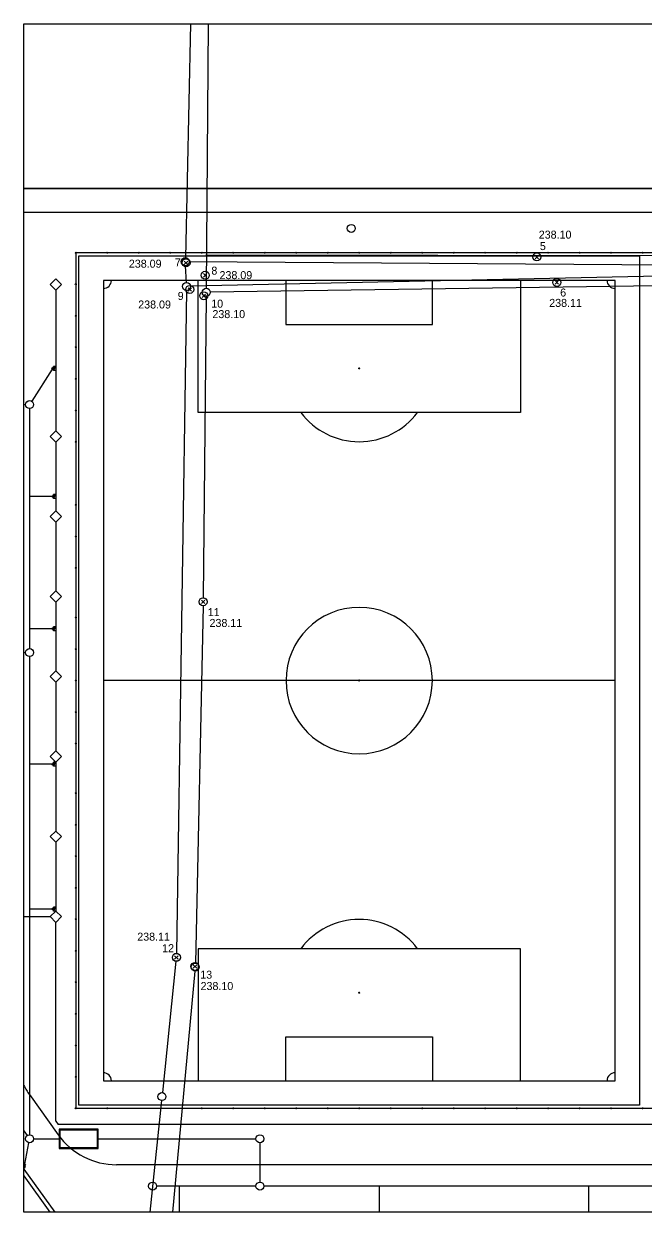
# Model space of a CAD drawing. Extents: x -264125 to -263915, y -1242307 to -1242159.
# Drawn here: x -264124.6 to -264047.1, y -1242307.4 to -1242158.9 of the extents above; entities that cross this region are included whole.
import ezdxf

# ---------------------------------------------------------------- set-up
doc = ezdxf.new("R2010")
doc.units = 0
for name, color, linetype in [('KFA_BODY_CISLO', 7, 'Continuous'), ('KFA_BODY_SYMBOL', 7, 'Continuous'), ('KFA_BODY_VYSKA', 7, 'Continuous'), ('KFA_JESTV_IS_DSP', 7, 'Continuous'), ('KFA_SITUACIA_DSP', 7, 'Continuous'), ('KFA_SO_40-3_SACHTY_POKLOPY', 7, 'Continuous'), ('RAM_NA_TLAC_A3_1-500', 7, 'Continuous')]:
    doc.layers.add(name, color=color, linetype=linetype)

msp = doc.modelspace()

# ---------------------------------------------------------------- linework, layer by layer
at = {"layer": 'KFA_BODY_SYMBOL'}
for p, q in [((-264104.51, -1242189), (-264104.06, -1242188.56)), ((-264104.06, -1242189), (-264104.51, -1242188.56)), ((-264060.62, -1242188.27), (-264060.18, -1242187.83)), ((-264060.18, -1242188.27), (-264060.62, -1242187.83)), ((-264102.1, -1242190.56), (-264101.66, -1242190.12)), ((-264101.66, -1242190.56), (-264102.1, -1242190.12)), ((-264104.03, -1242192.33), (-264103.59, -1242191.89)), ((-264103.59, -1242192.33), (-264104.03, -1242191.89)), ((-264058.12, -1242191.45), (-264057.68, -1242191.01)), ((-264057.68, -1242191.45), (-264058.12, -1242191.01)), ((-264102.28, -1242193.12), (-264101.84, -1242192.68)), ((-264101.84, -1242193.12), (-264102.28, -1242192.68)), ((-264102.36, -1242231.36), (-264101.92, -1242230.92)), ((-264101.92, -1242231.36), (-264102.36, -1242230.92)), ((-264105.72, -1242275.8), (-264105.27, -1242275.36)), ((-264105.27, -1242275.8), (-264105.72, -1242275.36)), ((-264103.38, -1242276.92), (-264102.94, -1242276.48)), ((-264102.94, -1242276.92), (-264103.38, -1242276.48))]:
    msp.add_line(p, q, dxfattribs=at)
at = {"layer": 'KFA_JESTV_IS_DSP'}
for p, q in [((-264103.74, -1242158.91), (-264104.36, -1242188.14)), ((-264101.53, -1242158.91), (-264101.75, -1242191.96)), ((-264014.6, -1242189.3), (-264103.87, -1242188.64)), ((-264014.74, -1242187.97), (-264101.79, -1242187.81)), ((-264104.37, -1242189.14), (-264104.25, -1242191.23)), ((-264045.1, -1242190.47), (-264103.72, -1242191.72)), ((-264045.33, -1242191.64), (-264101.25, -1242192.45)), ((-264104.23, -1242192.23), (-264105.48, -1242275.06)), ((-264101.76, -1242192.96), (-264102.14, -1242230.64)), ((-264102.15, -1242231.64), (-264103.11, -1242276.28)), ((-264105.54, -1242276.06), (-264107.24, -1242292.46)), ((-264103.16, -1242277.28), (-264105.98, -1242307.41)), ((-264107.35, -1242293.45), (-264108.79, -1242307.41))]:
    msp.add_line(p, q, dxfattribs=at)
for centre in [(-264083.61, -1242184.48), (-264104.37, -1242188.64), (-264104.22, -1242191.73), (-264101.75, -1242192.46), (-264102.14, -1242231.14), (-264105.49, -1242275.56), (-264103.12, -1242276.78), (-264107.29, -1242292.96)]:
    msp.add_circle(centre, 0.5, dxfattribs=at)
at = {"layer": 'KFA_SITUACIA_DSP'}
for p, q in [((-264077.23, -1242179.48), (-264124.58, -1242179.48)), ((-264124.58, -1242179.48), (-263959.47, -1242179.48)), ((-263959.47, -1242179.48), (-264124.58, -1242179.48)), ((-263959.47, -1242179.48), (-264077.23, -1242179.48)), ((-264045.2, -1242182.48), (-264124.58, -1242182.48)), ((-264118.01, -1242187.53), (-264118.13, -1242187.53)), ((-264118.07, -1242187.59), (-264118.07, -1242187.47)), ((-263972.07, -1242187.53), (-264118.07, -1242187.53)), ((-264118.07, -1242187.53), (-264118.07, -1242294.43)), ((-264114.07, -1242187.53), (-264114.19, -1242187.53)), ((-264114.13, -1242187.59), (-264114.13, -1242187.47)), ((-264110.13, -1242187.53), (-264110.25, -1242187.53)), ((-264110.19, -1242187.59), (-264110.19, -1242187.47)), ((-264106.19, -1242187.53), (-264106.31, -1242187.53)), ((-264106.25, -1242187.59), (-264106.25, -1242187.47)), ((-264102.25, -1242187.53), (-264102.37, -1242187.53)), ((-264102.31, -1242187.59), (-264102.31, -1242187.47)), ((-264098.31, -1242187.53), (-264098.43, -1242187.53)), ((-264098.37, -1242187.59), (-264098.37, -1242187.47)), ((-264094.37, -1242187.53), (-264094.49, -1242187.53)), ((-264094.43, -1242187.59), (-264094.43, -1242187.47)), ((-264090.44, -1242187.53), (-264090.56, -1242187.53)), ((-264090.5, -1242187.59), (-264090.5, -1242187.47)), ((-264086.5, -1242187.53), (-264086.62, -1242187.53)), ((-264086.56, -1242187.59), (-264086.56, -1242187.47)), ((-264082.56, -1242187.53), (-264082.68, -1242187.53)), ((-264082.62, -1242187.59), (-264082.62, -1242187.47)), ((-264078.62, -1242187.53), (-264078.74, -1242187.53)), ((-264078.68, -1242187.59), (-264078.68, -1242187.47)), ((-264074.68, -1242187.53), (-264074.8, -1242187.53)), ((-264074.74, -1242187.59), (-264074.74, -1242187.47)), ((-264070.74, -1242187.53), (-264070.86, -1242187.53)), ((-264070.8, -1242187.59), (-264070.8, -1242187.47)), ((-264066.8, -1242187.53), (-264066.92, -1242187.53)), ((-264066.86, -1242187.59), (-264066.86, -1242187.47)), ((-264062.86, -1242187.53), (-264062.98, -1242187.53)), ((-264062.92, -1242187.59), (-264062.92, -1242187.47)), ((-264058.92, -1242187.53), (-264059.04, -1242187.53)), ((-264058.98, -1242187.59), (-264058.98, -1242187.47)), ((-264054.99, -1242187.53), (-264055.11, -1242187.53)), ((-264055.05, -1242187.59), (-264055.05, -1242187.47)), ((-264051.05, -1242187.53), (-264051.17, -1242187.53)), ((-264051.11, -1242187.59), (-264051.11, -1242187.47)), ((-264047.11, -1242187.53), (-264047.23, -1242187.53)), ((-264047.17, -1242187.59), (-264047.17, -1242187.47)), ((-264117.67, -1242187.93), (-264047.57, -1242187.93)), ((-264117.67, -1242294.03), (-264117.67, -1242187.93)), ((-264047.57, -1242187.93), (-264047.57, -1242294.03)), ((-264121.27, -1242191.48), (-264120.57, -1242190.78)), ((-264120.57, -1242192.19), (-264121.27, -1242191.48)), ((-264120.57, -1242190.78), (-264119.86, -1242191.48)), ((-264119.86, -1242191.48), (-264120.57, -1242192.19)), ((-264118.01, -1242191.47), (-264118.13, -1242191.47)), ((-264118.07, -1242191.41), (-264118.07, -1242191.53)), ((-264050.62, -1242190.98), (-264114.62, -1242190.98)), ((-264114.62, -1242190.98), (-264114.62, -1242290.98)), ((-264102.78, -1242207.48), (-264102.78, -1242190.98)), ((-264091.78, -1242190.98), (-264091.78, -1242196.48)), ((-264073.46, -1242196.48), (-264073.46, -1242190.98)), ((-264062.46, -1242190.98), (-264062.46, -1242207.48)), ((-264050.62, -1242290.98), (-264050.62, -1242190.98)), ((-264120.57, -1242192.19), (-264120.57, -1242209.78)), ((-264118.01, -1242195.41), (-264118.13, -1242195.41)), ((-264118.07, -1242195.35), (-264118.07, -1242195.47)), ((-264091.78, -1242196.48), (-264073.46, -1242196.48)), ((-264118.01, -1242199.34), (-264118.13, -1242199.34)), ((-264118.07, -1242199.28), (-264118.07, -1242199.4)), ((-264121.01, -1242202.07), (-264123.58, -1242206.08)), ((-264120.86, -1242202.23), (-264120.86, -1242201.73)), ((-264120.86, -1242201.73), (-264120.57, -1242201.73)), ((-264120.86, -1242202.23), (-264120.57, -1242201.73)), ((-264120.86, -1242202.23), (-264120.57, -1242201.73)), ((-264120.57, -1242201.73), (-264120.86, -1242201.73)), ((-264120.86, -1242201.73), (-264120.86, -1242202.23)), ((-264120.57, -1242202.23), (-264120.86, -1242202.23)), ((-264120.57, -1242201.73), (-264120.57, -1242202.23)), ((-264118.01, -1242203.28), (-264118.13, -1242203.28)), ((-264118.07, -1242203.22), (-264118.07, -1242203.34)), ((-264124.58, -1242206.48), (-264124.35, -1242206.48)), ((-264123.85, -1242207), (-264123.85, -1242236.98)), ((-264118.01, -1242207.22), (-264118.13, -1242207.22)), ((-264118.07, -1242207.16), (-264118.07, -1242207.28)), ((-264062.46, -1242207.48), (-264102.78, -1242207.48)), ((-264121.27, -1242210.48), (-264120.57, -1242209.78)), ((-264120.57, -1242209.78), (-264119.86, -1242210.48)), ((-264120.57, -1242211.19), (-264121.27, -1242210.48)), ((-264119.86, -1242210.48), (-264120.57, -1242211.19)), ((-264120.57, -1242211.19), (-264120.57, -1242219.77)), ((-264118.01, -1242211.16), (-264118.13, -1242211.16)), ((-264118.07, -1242211.1), (-264118.07, -1242211.22)), ((-264121.06, -1242217.98), (-264123.85, -1242217.98)), ((-264120.86, -1242218.23), (-264120.86, -1242217.73)), ((-264120.86, -1242217.73), (-264120.57, -1242217.73)), ((-264120.86, -1242218.23), (-264120.57, -1242217.73)), ((-264120.86, -1242218.23), (-264120.57, -1242217.73)), ((-264120.57, -1242217.73), (-264120.86, -1242217.73)), ((-264120.86, -1242217.73), (-264120.86, -1242218.23)), ((-264120.57, -1242218.23), (-264120.86, -1242218.23)), ((-264120.57, -1242217.73), (-264120.57, -1242218.23)), ((-264121.27, -1242220.48), (-264120.57, -1242219.78)), ((-264120.57, -1242219.78), (-264119.86, -1242220.48)), ((-264118.01, -1242219.03), (-264118.13, -1242219.03)), ((-264118.07, -1242218.97), (-264118.07, -1242219.09)), ((-264120.57, -1242221.19), (-264121.27, -1242220.48)), ((-264119.86, -1242220.48), (-264120.57, -1242221.19)), ((-264120.57, -1242221.19), (-264120.57, -1242229.77)), ((-264118.01, -1242222.97), (-264118.13, -1242222.97)), ((-264118.07, -1242222.91), (-264118.07, -1242223.03)), ((-264118.01, -1242226.91), (-264118.13, -1242226.91)), ((-264118.07, -1242226.85), (-264118.07, -1242226.97)), ((-264121.27, -1242230.48), (-264120.57, -1242229.78)), ((-264120.57, -1242231.19), (-264121.27, -1242230.48)), ((-264120.57, -1242229.78), (-264119.86, -1242230.48)), ((-264119.86, -1242230.48), (-264120.57, -1242231.19)), ((-264120.57, -1242231.19), (-264120.57, -1242239.77)), ((-264118.01, -1242233.11), (-264118.13, -1242233.11)), ((-264118.07, -1242233.05), (-264118.07, -1242233.17)), ((-264121.06, -1242234.5), (-264123.85, -1242234.5)), ((-264120.86, -1242234.75), (-264120.86, -1242234.25)), ((-264120.86, -1242234.25), (-264120.57, -1242234.25)), ((-264120.86, -1242234.75), (-264120.57, -1242234.25)), ((-264120.86, -1242234.75), (-264120.57, -1242234.25)), ((-264120.57, -1242234.25), (-264120.86, -1242234.25)), ((-264120.86, -1242234.25), (-264120.86, -1242234.75)), ((-264120.57, -1242234.75), (-264120.86, -1242234.75)), ((-264120.57, -1242234.25), (-264120.57, -1242234.75)), ((-264124.58, -1242237.48), (-264124.35, -1242237.48)), ((-264123.85, -1242237.98), (-264123.85, -1242297.74)), ((-264118.01, -1242237.04), (-264118.13, -1242237.04)), ((-264118.07, -1242236.98), (-264118.07, -1242237.1)), ((-264121.27, -1242240.48), (-264120.57, -1242239.78)), ((-264120.57, -1242241.19), (-264121.27, -1242240.48)), ((-264120.57, -1242239.78), (-264119.86, -1242240.48)), ((-264119.86, -1242240.48), (-264120.57, -1242241.19)), ((-264118.01, -1242240.98), (-264118.13, -1242240.98)), ((-264118.07, -1242241.04), (-264118.07, -1242240.92)), ((-264050.62, -1242240.98), (-264114.62, -1242240.98)), ((-264120.57, -1242241.19), (-264120.57, -1242249.77)), ((-264118.01, -1242244.92), (-264118.13, -1242244.92)), ((-264118.07, -1242244.98), (-264118.07, -1242244.86)), ((-264121.27, -1242250.48), (-264120.57, -1242249.78)), ((-264120.57, -1242249.78), (-264119.86, -1242250.48)), ((-264118.01, -1242248.86), (-264118.13, -1242248.86)), ((-264118.07, -1242248.92), (-264118.07, -1242248.8)), ((-264121.06, -1242251.44), (-264123.85, -1242251.44)), ((-264120.57, -1242251.19), (-264121.27, -1242250.48)), ((-264120.86, -1242251.69), (-264120.86, -1242251.19)), ((-264120.86, -1242251.19), (-264120.57, -1242251.19)), ((-264120.86, -1242251.69), (-264120.57, -1242251.19)), ((-264120.86, -1242251.69), (-264120.57, -1242251.19)), ((-264120.57, -1242251.19), (-264120.86, -1242251.19)), ((-264120.86, -1242251.19), (-264120.86, -1242251.69)), ((-264119.86, -1242250.48), (-264120.57, -1242251.19)), ((-264120.57, -1242251.19), (-264120.57, -1242251.69)), ((-264120.57, -1242251.19), (-264120.57, -1242259.78)), ((-264120.57, -1242251.69), (-264120.86, -1242251.69)), ((-264118.01, -1242255.06), (-264118.13, -1242255.06)), ((-264118.07, -1242255.12), (-264118.07, -1242255)), ((-264121.27, -1242260.48), (-264120.57, -1242259.78)), ((-264120.57, -1242259.78), (-264119.86, -1242260.48)), ((-264118.01, -1242258.99), (-264118.13, -1242258.99)), ((-264118.07, -1242259.05), (-264118.07, -1242258.93)), ((-264120.57, -1242261.19), (-264121.27, -1242260.48)), ((-264119.86, -1242260.48), (-264120.57, -1242261.19)), ((-264120.57, -1242261.19), (-264120.57, -1242269.77)), ((-264118.01, -1242262.93), (-264118.13, -1242262.93)), ((-264118.07, -1242262.99), (-264118.07, -1242262.87)), ((-264118.01, -1242266.87), (-264118.13, -1242266.87)), ((-264118.07, -1242266.93), (-264118.07, -1242266.81)), ((-264120.86, -1242269.78), (-264120.86, -1242269.28)), ((-264120.86, -1242269.28), (-264120.57, -1242269.28)), ((-264120.86, -1242269.78), (-264120.57, -1242269.28)), ((-264120.86, -1242269.78), (-264120.57, -1242269.28)), ((-264120.57, -1242269.28), (-264120.86, -1242269.28)), ((-264120.86, -1242269.28), (-264120.86, -1242269.78)), ((-264120.57, -1242269.28), (-264120.57, -1242269.78)), ((-264124.58, -1242270.48), (-264121.27, -1242270.48)), ((-264121.06, -1242269.53), (-264123.85, -1242269.53)), ((-264121.27, -1242270.48), (-264120.57, -1242269.78)), ((-264120.57, -1242271.19), (-264121.27, -1242270.48)), ((-264120.57, -1242269.78), (-264120.86, -1242269.78)), ((-264120.57, -1242269.78), (-264119.86, -1242270.48)), ((-264119.86, -1242270.48), (-264120.57, -1242271.19)), ((-264118.01, -1242270.81), (-264118.13, -1242270.81)), ((-264118.07, -1242270.87), (-264118.07, -1242270.75)), ((-264120.57, -1242296.04), (-264120.57, -1242271.19)), ((-264120.57, -1242271.19), (-264120.57, -1242271.19)), ((-264118.01, -1242274.74), (-264118.13, -1242274.74)), ((-264118.07, -1242274.8), (-264118.07, -1242274.68)), ((-264062.46, -1242274.48), (-264102.78, -1242274.48)), ((-264102.78, -1242274.48), (-264102.78, -1242290.98)), ((-264062.46, -1242290.98), (-264062.46, -1242274.48)), ((-264118.01, -1242278.68), (-264118.13, -1242278.68)), ((-264118.07, -1242278.74), (-264118.07, -1242278.62)), ((-264118.01, -1242282.62), (-264118.13, -1242282.62)), ((-264118.07, -1242282.68), (-264118.07, -1242282.56)), ((-264091.78, -1242290.98), (-264091.78, -1242285.48)), ((-264091.78, -1242285.48), (-264073.46, -1242285.48)), ((-264073.46, -1242285.48), (-264073.46, -1242290.98)), ((-264118.01, -1242286.56), (-264118.13, -1242286.56)), ((-264118.07, -1242286.62), (-264118.07, -1242286.5)), ((-264118.01, -1242290.49), (-264118.13, -1242290.49)), ((-264118.07, -1242290.55), (-264118.07, -1242290.43)), ((-264114.62, -1242290.98), (-264050.62, -1242290.98)), ((-264123.87, -1242292.72), (-264120.27, -1242297.74)), ((-264118.01, -1242294.43), (-264118.13, -1242294.43)), ((-264118.07, -1242294.49), (-264118.07, -1242294.37)), ((-264118.07, -1242294.43), (-264045.12, -1242294.43)), ((-264047.57, -1242294.03), (-264117.67, -1242294.03)), ((-264114.07, -1242294.43), (-264114.19, -1242294.43)), ((-264114.13, -1242294.49), (-264114.13, -1242294.37)), ((-264102.25, -1242294.43), (-264102.37, -1242294.43)), ((-264102.31, -1242294.49), (-264102.31, -1242294.37)), ((-264098.31, -1242294.43), (-264098.43, -1242294.43)), ((-264098.37, -1242294.49), (-264098.37, -1242294.37)), ((-264094.37, -1242294.43), (-264094.49, -1242294.43)), ((-264094.43, -1242294.49), (-264094.43, -1242294.37)), ((-264090.44, -1242294.43), (-264090.56, -1242294.43)), ((-264090.5, -1242294.49), (-264090.5, -1242294.37)), ((-264086.5, -1242294.43), (-264086.62, -1242294.43)), ((-264086.56, -1242294.49), (-264086.56, -1242294.37)), ((-264082.56, -1242294.43), (-264082.68, -1242294.43)), ((-264082.62, -1242294.49), (-264082.62, -1242294.37)), ((-264078.62, -1242294.43), (-264078.74, -1242294.43)), ((-264078.68, -1242294.49), (-264078.68, -1242294.37)), ((-264074.68, -1242294.43), (-264074.8, -1242294.43)), ((-264074.74, -1242294.49), (-264074.74, -1242294.37)), ((-264070.74, -1242294.43), (-264070.86, -1242294.43)), ((-264070.8, -1242294.49), (-264070.8, -1242294.37)), ((-264066.8, -1242294.43), (-264066.92, -1242294.43)), ((-264066.86, -1242294.49), (-264066.86, -1242294.37)), ((-264062.86, -1242294.43), (-264062.98, -1242294.43)), ((-264062.92, -1242294.49), (-264062.92, -1242294.37)), ((-264058.92, -1242294.43), (-264059.04, -1242294.43)), ((-264058.98, -1242294.49), (-264058.98, -1242294.37)), ((-264054.99, -1242294.43), (-264055.11, -1242294.43)), ((-264055.05, -1242294.49), (-264055.05, -1242294.37)), ((-264051.05, -1242294.43), (-264051.17, -1242294.43)), ((-264051.11, -1242294.49), (-264051.11, -1242294.37)), ((-264047.11, -1242294.43), (-264047.23, -1242294.43)), ((-264047.17, -1242294.49), (-264047.17, -1242294.37)), ((-264120.57, -1242296.04), (-264120.28, -1242296.43)), ((-264124.58, -1242297.23), (-264124.15, -1242297.83)), ((-264124.58, -1242297.23), (-264124.15, -1242297.83)), ((-264120.02, -1242296.43), (-264120.28, -1242296.43)), ((-264120.15, -1242297.04), (-264120.15, -1242299.44)), ((-264115.25, -1242297.04), (-264120.15, -1242297.04)), ((-264115.35, -1242297.14), (-264120.05, -1242297.14)), ((-264120.05, -1242297.14), (-264120.05, -1242299.34)), ((-264019.58, -1242296.43), (-264120.02, -1242296.43)), ((-264115.35, -1242299.34), (-264115.35, -1242297.14)), ((-264115.25, -1242299.44), (-264115.25, -1242297.04)), ((-264124.44, -1242301.41), (-264123.95, -1242298.73)), ((-264123.35, -1242298.24), (-264120.15, -1242298.24)), ((-264115.25, -1242298.24), (-264095.53, -1242298.24)), ((-264095.03, -1242298.74), (-264095.03, -1242303.65)), ((-264120.15, -1242299.44), (-264115.25, -1242299.44)), ((-264120.05, -1242299.34), (-264115.35, -1242299.34)), ((-264124.58, -1242301.52), (-264124.4, -1242301.77)), ((-264124.4, -1242301.77), (-264124.58, -1242301.52)), ((-264124.4, -1242301.77), (-264124.58, -1242301.9)), ((-264124.58, -1242301.9), (-264124.4, -1242301.77)), ((-264019.58, -1242301.48), (-264112.96, -1242301.48)), ((-264124.58, -1242302.02), (-264120.7, -1242307.41)), ((-264124.58, -1242302.87), (-264121.32, -1242307.41)), ((-264095.53, -1242304.15), (-264107.96, -1242304.15)), ((-264105.08, -1242307.41), (-264105.08, -1242304.15)), ((-264045.53, -1242304.15), (-264094.53, -1242304.15)), ((-264080.08, -1242307.41), (-264080.08, -1242304.15)), ((-264053.91, -1242307.41), (-264053.91, -1242304.15))]:
    msp.add_line(p, q, dxfattribs=at)
for centre, radius in [((-264118.07, -1242187.53), 0.06), ((-264114.13, -1242187.53), 0.06), ((-264110.19, -1242187.53), 0.06), ((-264106.25, -1242187.53), 0.06), ((-264102.31, -1242187.53), 0.06), ((-264098.37, -1242187.53), 0.06), ((-264094.43, -1242187.53), 0.06), ((-264090.5, -1242187.53), 0.06), ((-264086.56, -1242187.53), 0.06), ((-264082.62, -1242187.53), 0.06), ((-264078.68, -1242187.53), 0.06), ((-264074.74, -1242187.53), 0.06), ((-264070.8, -1242187.53), 0.06), ((-264066.86, -1242187.53), 0.06), ((-264062.92, -1242187.53), 0.06), ((-264058.98, -1242187.53), 0.06), ((-264055.05, -1242187.53), 0.06), ((-264051.11, -1242187.53), 0.06), ((-264047.17, -1242187.53), 0.06), ((-264118.07, -1242191.47), 0.06), ((-264118.07, -1242195.41), 0.06), ((-264118.07, -1242199.34), 0.06), ((-264120.96, -1242201.98), 0.1), ((-264082.62, -1242201.98), 0.06), ((-264118.07, -1242203.28), 0.06), ((-264123.85, -1242206.5), 0.5), ((-264118.07, -1242207.22), 0.06), ((-264118.07, -1242211.16), 0.06), ((-264120.96, -1242217.98), 0.1), ((-264118.07, -1242219.03), 0.06), ((-264118.07, -1242222.97), 0.06), ((-264118.07, -1242226.91), 0.06), ((-264118.07, -1242233.11), 0.06), ((-264120.96, -1242234.5), 0.1), ((-264123.85, -1242237.48), 0.5), ((-264118.07, -1242237.04), 0.06), ((-264118.07, -1242240.98), 0.06), ((-264118.07, -1242244.92), 0.06), ((-264118.07, -1242248.86), 0.06), ((-264120.96, -1242251.44), 0.1), ((-264118.07, -1242255.06), 0.06), ((-264118.07, -1242258.99), 0.06), ((-264118.07, -1242262.93), 0.06), ((-264118.07, -1242266.87), 0.06), ((-264120.96, -1242269.53), 0.1), ((-264118.07, -1242270.81), 0.06), ((-264118.07, -1242274.74), 0.06), ((-264118.07, -1242278.68), 0.06), ((-264082.62, -1242279.98), 0.06), ((-264118.07, -1242282.62), 0.06), ((-264118.07, -1242286.56), 0.06), ((-264118.07, -1242290.49), 0.06), ((-264118.07, -1242294.43), 0.06), ((-264114.13, -1242294.43), 0.06), ((-264102.31, -1242294.43), 0.06), ((-264098.37, -1242294.43), 0.06), ((-264094.43, -1242294.43), 0.06), ((-264090.5, -1242294.43), 0.06), ((-264086.56, -1242294.43), 0.06), ((-264082.62, -1242294.43), 0.06), ((-264078.68, -1242294.43), 0.06), ((-264074.74, -1242294.43), 0.06), ((-264070.8, -1242294.43), 0.06), ((-264066.86, -1242294.43), 0.06), ((-264062.92, -1242294.43), 0.06), ((-264058.98, -1242294.43), 0.06), ((-264055.05, -1242294.43), 0.06), ((-264051.11, -1242294.43), 0.06), ((-264047.17, -1242294.43), 0.06), ((-264123.85, -1242298.24), 0.5), ((-264095.03, -1242298.24), 0.5), ((-264124.46, -1242301.51), 0.1), ((-264108.46, -1242304.15), 0.5), ((-264095.03, -1242304.15), 0.5)]:
    msp.add_circle(centre, radius, dxfattribs=at)
for centre, radius, start, end in [((-264114.62, -1242190.98), 1, 270, 360), ((-264050.62, -1242190.98), 1, 180, 270), ((-264082.62, -1242201.98), 0.0303, 90, 270), ((-264082.62, -1242201.98), 0.0303, 270, 90), ((-264082.62, -1242201.98), 9.15, 216.9482, 323.0518), ((-264082.62, -1242240.98), 9.15, 360, 180), ((-264082.62, -1242240.98), 9.15, 180, 360), ((-264082.62, -1242240.98), 0.0605, 90, 270), ((-264082.62, -1242240.98), 0.0605, 270, 90), ((-264082.62, -1242279.98), 9.15, 36.9482, 143.0518), ((-264082.62, -1242279.98), 0.0303, 90, 270), ((-264082.62, -1242279.98), 0.0303, 270, 90), ((-264114.62, -1242290.98), 1, 0, 90), ((-264050.62, -1242290.98), 1, 90, 180), ((-264116.57, -1242287.47), 9, 207.1096, 215.724), ((-264112.96, -1242292.48), 9, 215.724, 270)]:
    msp.add_arc(centre, radius, start, end, dxfattribs=at)
at = {"layer": 'KFA_SO_40-3_SACHTY_POKLOPY'}
for centre in [(-264060.4, -1242188.05), (-264104.28, -1242188.78), (-264101.88, -1242190.34), (-264103.81, -1242192.11), (-264057.9, -1242191.23), (-264102.06, -1242192.9), (-264102.14, -1242231.14), (-264105.49, -1242275.58), (-264103.16, -1242276.7)]:
    msp.add_circle(centre, 0.5, dxfattribs=at)
at = {"layer": 'RAM_NA_TLAC_A3_1-500'}
msp.add_lwpolyline([(-264124.58, -1242158.91), (-263914.58, -1242158.91), (-263914.58, -1242307.41), (-264124.58, -1242307.41)], close=True, dxfattribs=at)

# ---------------------------------------------------------------- texts
at = {"layer": 'KFA_BODY_CISLO'}
for s, p in [('5', (-264060.02, -1242187.19)), ('7', (-264105.67, -1242189.22)), ('8', (-264101.11, -1242190.26)), ('6', (-264057.48, -1242192.99)), ('9', (-264105.32, -1242193.42)), ('10', (-264101.13, -1242194.39)), ('11', (-264101.56, -1242232.93)), ('12', (-264107.27, -1242274.92)), ('13', (-264102.5, -1242278.23))]:
    msp.add_text(s, height=1, dxfattribs=at).set_placement(p)
at = {"layer": 'KFA_BODY_VYSKA'}
for s, p in [('238.10', (-264060.16, -1242185.76)), ('238.09', (-264111.43, -1242189.39)), ('238.09', (-264100.09, -1242190.82)), ('238.09', (-264110.26, -1242194.49)), ('238.11', (-264058.85, -1242194.29)), ('238.10', (-264100.98, -1242195.69)), ('238.11', (-264101.34, -1242234.28)), ('238.11', (-264110.38, -1242273.48)), ('238.10', (-264102.46, -1242279.65))]:
    msp.add_text(s, height=1, dxfattribs=at).set_placement(p)

doc.saveas('drawing.dxf')
